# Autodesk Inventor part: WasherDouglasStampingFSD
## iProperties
Company: jsm
Author: XMN5642
Shininess: 41.0
PropertySet Name: _Private Model Information
Length Units: 11272
Angle Units: 11283
Time Units: 11279
Mass Units: 11290
Length Display Precision: 3
Angle Display Precision: 2
Compacted: True
Created: 2001-04
Part Number: WasherDouglasStampingFSD
Document SubType Name: Modeling
Designer: XMN5642
Material: Steel, Mild
Control State: 0
Master: False
Checked Out: False
PropertySet Name: Design Tracking Control
Density: 0.0
Volumn: 0.0
Area: 0.0
PropertySet Name: Model Information
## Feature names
1. Extrusion1
2. FlatCut [Extrusion]
